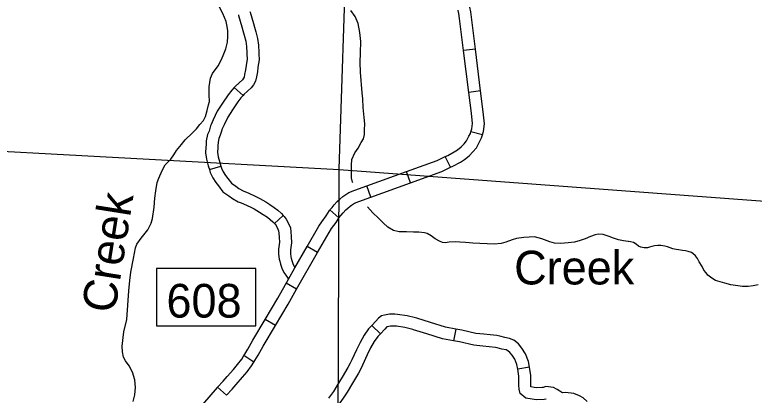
# Model space of a CAD drawing. Extents: x -492261 to -432772, y 1441225 to 1452922.
# Drawn here: x -463909.6 to -463644.7, y 1451578.4 to 1451714.7 of the extents above; entities that cross this region are included whole.
import ezdxf

# ---------------------------------------------------------------- set-up
doc = ezdxf.new("R2010")
doc.units = 0
doc.layers.add('Default', color=7, linetype='Continuous')

msp = doc.modelspace()

# ---------------------------------------------------------------- linework, layer by layer
at = {"layer": 'Default'}
for p, q in [((-463744.56, 1451702.45), (-463748.82, 1451701.91)), ((-463831, 1451688.68), (-463827.77, 1451685.85)), ((-463742.67, 1451687.48), (-463746.92, 1451686.94)), ((-463742.04, 1451671.69), (-463746.16, 1451672.85)), ((-463753.53, 1451660.08), (-463755.37, 1451663.95)), ((-463839.88, 1451659.25), (-463835.76, 1451660.45)), ((-463767.78, 1451654.56), (-463769.24, 1451658.6)), ((-463781.97, 1451649.44), (-463783.43, 1451653.47)), ((-463793.44, 1451642.02), (-463796.69, 1451644.82)), ((-463816.57, 1451639.97), (-463813.41, 1451642.87)), ((-463801.12, 1451629.53), (-463804.84, 1451631.66)), ((-463808.62, 1451616.44), (-463812.34, 1451618.57)), ((-463816.23, 1451603.38), (-463819.92, 1451605.56)), ((-463781.68, 1451603.44), (-463778.59, 1451600.47)), ((-463751.58, 1451602.14), (-463752.38, 1451597.93)), ((-463823.9, 1451590.3), (-463827.51, 1451592.61)), ((-463725.17, 1451588.46), (-463729.4, 1451587.74)), ((-463833.74, 1451578.44), (-463836.93, 1451581.31))]:
    msp.add_line(p, q, dxfattribs=at)
for points in [[(-463790.72, 1451742.44), (-463793.52, 1451659.39), (-463794.14, 1451505.86), (-463793.73, 1451460.92)], [(-463839.88, 1451683.61), (-463839.97, 1451686.07), (-463839.99, 1451688.93), (-463839.51, 1451692.02), (-463838.79, 1451693.69), (-463836.77, 1451696.46), (-463835.7, 1451698.42), (-463834.98, 1451700.14), (-463834.03, 1451702.5), (-463833.43, 1451704.96), (-463833.22, 1451706.97), (-463833.25, 1451709.03), (-463833.49, 1451710.51), (-463833.91, 1451712.34), (-463835.08, 1451715.19), (-463836.13, 1451717.23), (-463836.65, 1451718.6), (-463837.24, 1451720.08), (-463837.48, 1451721.51)], [(-463825.36, 1451715.93), (-463825.3, 1451715.72), (-463824.11, 1451711.58), (-463823.76, 1451710.26), (-463823.27, 1451708.63), (-463822.64, 1451706.21), (-463822.24, 1451703.82), (-463822.17, 1451701.19), (-463822.15, 1451700.71)], [(-463788.51, 1451654.59), (-463788.59, 1451654.78), (-463788.89, 1451656.27), (-463788.92, 1451658.96), (-463789, 1451660.84), (-463788.79, 1451662.91), (-463787.79, 1451665.32), (-463786.61, 1451666.99), (-463785.43, 1451668.95), (-463784.65, 1451670.28), (-463784.32, 1451671.82), (-463784.28, 1451673.54), (-463784.19, 1451675.66), (-463784.44, 1451677.94), (-463784.71, 1451681.55), (-463784.86, 1451684.63), (-463785.11, 1451686.75), (-463785.7, 1451694.18), (-463785.9, 1451697.67), (-463785.71, 1451701.04), (-463785.64, 1451705.11), (-463786.02, 1451708.42), (-463786.56, 1451711.56), (-463787.62, 1451714.12), (-463789.18, 1451716.22)], [(-463748.82, 1451701.91), (-463750.27, 1451713.41), (-463750.45, 1451715.14), (-463750.7, 1451716.26), (-463750.74, 1451716.39)], [(-463744.56, 1451702.45), (-463746.01, 1451713.9), (-463746.21, 1451715.82), (-463746.57, 1451717.45), (-463746.71, 1451717.84)], [(-463829.48, 1451714.72), (-463829.42, 1451714.52), (-463828.24, 1451710.45), (-463827.89, 1451709.09), (-463827.39, 1451707.47), (-463826.83, 1451705.32), (-463826.52, 1451703.41), (-463826.45, 1451701.06), (-463826.44, 1451700.58)], [(-463742.67, 1451687.48), (-463744.56, 1451702.45)], [(-463826.44, 1451700.58), (-463826.39, 1451698.86), (-463826.73, 1451696.56), (-463826.89, 1451694.95), (-463827.25, 1451693.35), (-463827.42, 1451692.38), (-463827.65, 1451691.98), (-463828.06, 1451691.4), (-463830.54, 1451689.2), (-463831, 1451688.68)], [(-463822.15, 1451700.71), (-463822.09, 1451698.61), (-463822.47, 1451696.02), (-463822.66, 1451694.27), (-463823.04, 1451692.52), (-463823.33, 1451690.9), (-463824.04, 1451689.66), (-463824.85, 1451688.51), (-463827.5, 1451686.17), (-463827.77, 1451685.85)], [(-463746.92, 1451686.94), (-463748.82, 1451701.91)], [(-463831, 1451688.68), (-463831.85, 1451687.71), (-463833.18, 1451686.04), (-463835.11, 1451683.04), (-463837.04, 1451680.22), (-463838.47, 1451677.08), (-463839.25, 1451675.42)], [(-463746.16, 1451672.85), (-463745.89, 1451673.81), (-463745.63, 1451675.76), (-463745.99, 1451679.54), (-463746.92, 1451686.94)], [(-463742.04, 1451671.69), (-463741.68, 1451672.94), (-463741.31, 1451675.68), (-463741.72, 1451680.01), (-463742.67, 1451687.48)], [(-463827.77, 1451685.85), (-463828.56, 1451684.96), (-463829.69, 1451683.54), (-463831.54, 1451680.67), (-463833.29, 1451678.1), (-463834.58, 1451675.28), (-463835.36, 1451673.61)], [(-463844.51, 1451673.83), (-463843.33, 1451675.37), (-463841.95, 1451676.89), (-463841.26, 1451678.32), (-463840.61, 1451680.45), (-463840.13, 1451682.42), (-463839.88, 1451683.61)], [(-463537.11, 1451643.12), (-463640.85, 1451647.85), (-463793.35, 1451659.21), (-463942.76, 1451667.26), (-464094.29, 1451673.71), (-464247.02, 1451675.18)], [(-463871.08, 1451596.01), (-463870.56, 1451601.11), (-463869.41, 1451605.52), (-463868.72, 1451615.83), (-463868.36, 1451619.55), (-463867.99, 1451622.47), (-463867.07, 1451627.41), (-463866.31, 1451631.19), (-463865.87, 1451632.57), (-463864.3, 1451634.7), (-463861.93, 1451637.65), (-463860.7, 1451640.12), (-463860.21, 1451641.79), (-463859.68, 1451645.85), (-463859.43, 1451649), (-463859.11, 1451651.64), (-463858.52, 1451654.68), (-463858.02, 1451656.23), (-463856.79, 1451658.93), (-463855.73, 1451661), (-463853.7, 1451663.03), (-463852.57, 1451664.53), (-463851.62, 1451666.08), (-463849.87, 1451668.22), (-463848.52, 1451669.89), (-463845.87, 1451672.44), (-463844.51, 1451673.83)], [(-463839.25, 1451675.42), (-463839.49, 1451674.9), (-463840, 1451673.01), (-463840.54, 1451671.82), (-463841.04, 1451669.58), (-463841.08, 1451668.13), (-463841.17, 1451667.35), (-463841.21, 1451665.29), (-463840.96, 1451663.02), (-463840.27, 1451660.59), (-463839.88, 1451659.25)], [(-463835.36, 1451673.61), (-463835.45, 1451673.42), (-463835.95, 1451671.57), (-463836.45, 1451670.45), (-463836.77, 1451669.05), (-463836.8, 1451667.82), (-463836.89, 1451667.07), (-463836.92, 1451665.49), (-463836.74, 1451663.84), (-463836.15, 1451661.78), (-463835.76, 1451660.45)], [(-463755.37, 1451663.95), (-463754.49, 1451664.37), (-463752.15, 1451665.58), (-463750.95, 1451666.4), (-463749.7, 1451667.37), (-463748.62, 1451668.48), (-463747.75, 1451669.52), (-463746.85, 1451671.2), (-463746.34, 1451672.2), (-463746.16, 1451672.85)], [(-463753.53, 1451660.08), (-463752.59, 1451660.53), (-463749.94, 1451661.89), (-463748.42, 1451662.94), (-463746.84, 1451664.17), (-463745.44, 1451665.6), (-463744.17, 1451667.11), (-463743.05, 1451669.22), (-463742.33, 1451670.64), (-463742.04, 1451671.69)], [(-463769.24, 1451658.6), (-463758.29, 1451662.55), (-463756.57, 1451663.38), (-463755.37, 1451663.95)], [(-463835.76, 1451660.45), (-463835.56, 1451659.76), (-463834.91, 1451658.41), (-463834.11, 1451657.14), (-463833.26, 1451656.09), (-463831.99, 1451654.46), (-463830.39, 1451653.31), (-463829.28, 1451652.48), (-463827.76, 1451651.64), (-463826.94, 1451651.32)], [(-463767.78, 1451654.56), (-463756.62, 1451658.6), (-463754.72, 1451659.52), (-463753.53, 1451660.08)], [(-463839.88, 1451659.25), (-463839.57, 1451658.22), (-463838.66, 1451656.33), (-463837.61, 1451654.65), (-463836.62, 1451653.42), (-463834.99, 1451651.34), (-463832.92, 1451649.85), (-463831.62, 1451648.88), (-463829.58, 1451647.74), (-463828.48, 1451647.32)], [(-463783.43, 1451653.47), (-463769.24, 1451658.6)], [(-463781.97, 1451649.44), (-463767.78, 1451654.56)], [(-463796.69, 1451644.82), (-463795.93, 1451645.7), (-463795.14, 1451646.63), (-463794.08, 1451647.84), (-463793.11, 1451648.7), (-463792.03, 1451649.62), (-463791.32, 1451650.08), (-463789.9, 1451651.08), (-463787.81, 1451651.89), (-463783.43, 1451653.47)], [(-463826.94, 1451651.32), (-463826.01, 1451650.96), (-463823.17, 1451649.65), (-463821.76, 1451648.94), (-463819.65, 1451647.66), (-463818.21, 1451646.73), (-463816.68, 1451645.72), (-463815.33, 1451644.76), (-463814.05, 1451643.56), (-463813.41, 1451642.87)], [(-463793.44, 1451642.02), (-463792.68, 1451642.91), (-463791.89, 1451643.83), (-463791.03, 1451644.82), (-463790.3, 1451645.46), (-463789.46, 1451646.17), (-463788.92, 1451646.53), (-463787.86, 1451647.27), (-463786.31, 1451647.88), (-463781.97, 1451649.44)], [(-463828.48, 1451647.32), (-463827.68, 1451647.01), (-463825.04, 1451645.79), (-463823.84, 1451645.19), (-463821.91, 1451644.02), (-463820.55, 1451643.15), (-463819.1, 1451642.18), (-463818.04, 1451641.43), (-463817.1, 1451640.55), (-463816.57, 1451639.97)], [(-463804.84, 1451631.66), (-463800.62, 1451639.03), (-463799.61, 1451640.56), (-463798.05, 1451642.73), (-463796.88, 1451644.6), (-463796.69, 1451644.82)], [(-463643.23, 1451617.99), (-463645, 1451617.63), (-463646.88, 1451617.43), (-463648.87, 1451617.41), (-463650.58, 1451617.62), (-463652.98, 1451617.99), (-463655.21, 1451618.54), (-463658.48, 1451619.53), (-463659.85, 1451620.37), (-463661.23, 1451621.5), (-463661.93, 1451622.24), (-463662.73, 1451623.2), (-463663.32, 1451624.51), (-463664.36, 1451626.22), (-463665, 1451627.41), (-463665.75, 1451628.37), (-463666.62, 1451629.22), (-463667.13, 1451629.56), (-463668.28, 1451629.95), (-463669.31, 1451630.11), (-463670.39, 1451630.32), (-463671.76, 1451630.48), (-463672.62, 1451630.64), (-463673.76, 1451630.91), (-463674.79, 1451631.19), (-463675.77, 1451631.58), (-463676.68, 1451631.85), (-463678.06, 1451632.12), (-463679.2, 1451632.11), (-463680.33, 1451631.98), (-463681.36, 1451631.74), (-463682.21, 1451631.45), (-463682.95, 1451631.27), (-463684.09, 1451631.26), (-463685.29, 1451631.53), (-463686.09, 1451631.86), (-463687.01, 1451632.54), (-463687.93, 1451633.1), (-463689.02, 1451633.37), (-463689.76, 1451633.48), (-463689.88, 1451633.48), (-463691.53, 1451633.69), (-463693.3, 1451634.13), (-463695.13, 1451634.68), (-463696.62, 1451635.35), (-463698.8, 1451636.01), (-463700.57, 1451636.1), (-463701.59, 1451635.86), (-463703.35, 1451635.27), (-463705.28, 1451634.5), (-463707.05, 1451633.86), (-463709.04, 1451633.32), (-463711.37, 1451633.06), (-463713.99, 1451632.8), (-463716.22, 1451632.95), (-463717.88, 1451633.33), (-463720.8, 1451634.44), (-463723.37, 1451635.21), (-463727.19, 1451634.94), (-463729.87, 1451634.63), (-463731.35, 1451634.09), (-463733.62, 1451633.27), (-463735.32, 1451632.79), (-463737.89, 1451632.59), (-463740.34, 1451632.62), (-463742.97, 1451632.76), (-463745.42, 1451632.96), (-463748.1, 1451633.16), (-463750.16, 1451633.31), (-463751.64, 1451633.35), (-463753.98, 1451633.21), (-463755.35, 1451633.08), (-463756.37, 1451633.18), (-463757.46, 1451633.57), (-463758.95, 1451634.47), (-463760.45, 1451635.48), (-463761.82, 1451636.32), (-463762.85, 1451636.65), (-463764.79, 1451636.8), (-463766.74, 1451636.9), (-463769.19, 1451636.93), (-463771.87, 1451637.01), (-463773.93, 1451637.44), (-463775.94, 1451638.62), (-463777.55, 1451640.15), (-463779.22, 1451641.85), (-463781.35, 1451643.82), (-463783.27, 1451645.97)], [(-463813.41, 1451642.87), (-463813.06, 1451642.48), (-463812.31, 1451641.51), (-463811.39, 1451639.76), (-463810.84, 1451638.37), (-463810.71, 1451636.93), (-463810.55, 1451635.31), (-463810.42, 1451633.07), (-463810.83, 1451630.48), (-463810.82, 1451629.26), (-463810.65, 1451628), (-463810.53, 1451627.53)], [(-463801.12, 1451629.53), (-463796.97, 1451636.78), (-463796.08, 1451638.13), (-463794.49, 1451640.34), (-463793.42, 1451642.05), (-463793.44, 1451642.02)], [(-463816.57, 1451639.97), (-463816.35, 1451639.73), (-463815.93, 1451639.19), (-463815.29, 1451637.98), (-463815.06, 1451637.37), (-463814.98, 1451636.51), (-463814.82, 1451634.97), (-463814.72, 1451633.29), (-463815.12, 1451630.8), (-463815.11, 1451628.96), (-463814.86, 1451627.17), (-463814.68, 1451626.45)], [(-463809.2, 1451624.04), (-463804.84, 1451631.66)], [(-463808.62, 1451616.44), (-463801.12, 1451629.53)], [(-463814.68, 1451626.45), (-463814.41, 1451625.43), (-463813.91, 1451623.96), (-463813.19, 1451622.45), (-463812.47, 1451621.42), (-463811.52, 1451619.99)], [(-463810.53, 1451627.53), (-463810.31, 1451626.67), (-463809.93, 1451625.57), (-463809.2, 1451624.04)], [(-463858.81, 1451603.3), (-463823.24, 1451603.3), (-463823.24, 1451623.85), (-463858.81, 1451623.85), (-463858.81, 1451603.3)], [(-463819.92, 1451605.56), (-463815.38, 1451613.24), (-463811.52, 1451619.99), (-463809.2, 1451624.04)], [(-463816.23, 1451603.38), (-463811.68, 1451611.09), (-463808.62, 1451616.44)], [(-463765.97, 1451606.14), (-463769.04, 1451606.91), (-463772.42, 1451607.39), (-463773.47, 1451607.44), (-463775.31, 1451607.53), (-463777.1, 1451607.17), (-463778.2, 1451606.91), (-463779.32, 1451606.05), (-463780.19, 1451605), (-463781.68, 1451603.44)], [(-463827.51, 1451592.61), (-463827.18, 1451593.13), (-463826.09, 1451594.98), (-463824.3, 1451598.15), (-463819.92, 1451605.56)], [(-463751.58, 1451602.14), (-463755.3, 1451602.85), (-463760.65, 1451604.49), (-463765.55, 1451606.04), (-463765.97, 1451606.14)], [(-463823.9, 1451590.3), (-463823.53, 1451590.89), (-463822.38, 1451592.84), (-463820.59, 1451596), (-463816.23, 1451603.38)], [(-463781.68, 1451603.44), (-463782.84, 1451602.24), (-463784.47, 1451599.99), (-463785.9, 1451597.35), (-463787.16, 1451594.75), (-463788.82, 1451591.09), (-463789.44, 1451589.89)], [(-463767.02, 1451601.99), (-463769.86, 1451602.7), (-463772.81, 1451603.12), (-463773.67, 1451603.16), (-463774.99, 1451603.22), (-463776.17, 1451602.99), (-463776.32, 1451602.95), (-463776.33, 1451602.94), (-463776.98, 1451602.15), (-463778.59, 1451600.47)], [(-463752.38, 1451597.93), (-463756.33, 1451598.68), (-463761.92, 1451600.39), (-463766.72, 1451601.91), (-463767.02, 1451601.99)], [(-463736.84, 1451599.77), (-463739.24, 1451600.08), (-463741.57, 1451600.25), (-463744.42, 1451600.54), (-463749.37, 1451601.72), (-463751.58, 1451602.14)], [(-463778.59, 1451600.47), (-463779.54, 1451599.49), (-463780.83, 1451597.7), (-463782.09, 1451595.39), (-463783.28, 1451592.92), (-463784.97, 1451589.22), (-463785.63, 1451587.93)], [(-463725.17, 1451588.46), (-463725.53, 1451590.53), (-463726.57, 1451593.28), (-463727.92, 1451595.32), (-463729.17, 1451596.89), (-463730.79, 1451598.1), (-463732.29, 1451598.77), (-463734.05, 1451599.12), (-463735.85, 1451599.65), (-463736.84, 1451599.77)], [(-463737.38, 1451595.52), (-463739.67, 1451595.81), (-463741.95, 1451595.98), (-463745.14, 1451596.31), (-463750.27, 1451597.53), (-463752.38, 1451597.93)], [(-463867.17, 1451576.14), (-463866.56, 1451578.61), (-463866.36, 1451581.24), (-463866.62, 1451583.93), (-463867.39, 1451586.72), (-463868.61, 1451589), (-463869.94, 1451590.81), (-463870.58, 1451592.07), (-463871, 1451594.01), (-463871.08, 1451596.01)], [(-463729.4, 1451587.74), (-463729.68, 1451589.4), (-463730.41, 1451591.32), (-463731.39, 1451592.8), (-463732.18, 1451593.79), (-463732.96, 1451594.38), (-463733.58, 1451594.66), (-463735.08, 1451594.95), (-463736.74, 1451595.44), (-463737.38, 1451595.52)], [(-463836.93, 1451581.31), (-463834.95, 1451583.5), (-463833.48, 1451585.18), (-463831.19, 1451587.7), (-463829.74, 1451589.47), (-463828.29, 1451591.39), (-463827.51, 1451592.61)], [(-463833.74, 1451578.44), (-463831.75, 1451580.65), (-463830.28, 1451582.33), (-463827.95, 1451584.89), (-463826.37, 1451586.82), (-463824.77, 1451588.94), (-463823.9, 1451590.3)], [(-463789.44, 1451589.89), (-463790.22, 1451588.38), (-463792.32, 1451584.92), (-463794.15, 1451581.78), (-463795.44, 1451579.79), (-463797.21, 1451577.35)], [(-463720.3, 1451581.23), (-463720.6, 1451581.15), (-463722.56, 1451581.06), (-463723.55, 1451581.2), (-463724.58, 1451581.4), (-463724.64, 1451581.45), (-463724.67, 1451582.14), (-463724.7, 1451585.66), (-463725.04, 1451587.65), (-463725.17, 1451588.46)], [(-463785.63, 1451587.93), (-463786.48, 1451586.29), (-463788.64, 1451582.73), (-463790.5, 1451579.53), (-463791.91, 1451577.37), (-463793.73, 1451574.84)], [(-463719.23, 1451577.08), (-463719.95, 1451576.89), (-463722.77, 1451576.76), (-463724.27, 1451576.97), (-463726.5, 1451577.41), (-463728.51, 1451579.11), (-463728.88, 1451580.55), (-463728.96, 1451582.01), (-463728.99, 1451585.28), (-463729.26, 1451586.93), (-463729.4, 1451587.74)], [(-463846.8, 1451569.83), (-463836.99, 1451581.24), (-463836.93, 1451581.31)], [(-463704.55, 1451576.19), (-463705.9, 1451577.44), (-463707.22, 1451578.18), (-463709.32, 1451579.11), (-463712.3, 1451579.38), (-463713.35, 1451579.29), (-463713.56, 1451579.36), (-463714.27, 1451579.94), (-463715.22, 1451580.46), (-463716.55, 1451581.18), (-463719.28, 1451581.5), (-463720.3, 1451581.23)]]:
    msp.add_lwpolyline(points, dxfattribs=at)
msp.add_lwpolyline([(-463858.81, 1451603.3), (-463823.24, 1451603.3), (-463823.24, 1451623.85), (-463858.81, 1451623.85)], close=True, dxfattribs=at)

# ---------------------------------------------------------------- texts
msp.add_text('Creek', height=12.069, rotation=81, dxfattribs=at).set_placement((-463873.77, 1451607.46))
for s, height, p in [('Creek', 12.069, (-463730.67, 1451618.12)), ('608', 12.057, (-463855.24, 1451606.25))]:
    msp.add_text(s, height=height, dxfattribs=at).set_placement(p)

doc.saveas('drawing.dxf')
